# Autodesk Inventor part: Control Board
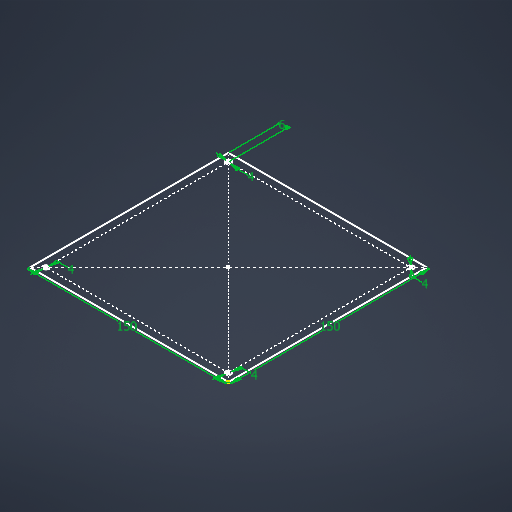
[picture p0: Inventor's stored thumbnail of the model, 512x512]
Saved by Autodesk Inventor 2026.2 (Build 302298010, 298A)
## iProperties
Created: 2026-04
Part Number: Control Board
Material: 일반
Document SubType Name: Modeling
Designer: work
Density: 1 g/cm^3
Appearance: 기본값
Author: work
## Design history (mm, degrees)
sketch "스케치1"
  geometry: L1 (150, -150)-(0, -150); L2 (0, -150)-(0, 0); L3 (0, 0)-(150, 0); L4 (150, 0)-(150, -150); L5 (150, -150)-(0, 0); L6 (0, -150)-(150, 0); L7 (6, -6)-(144, -6); L8 (144, -6)-(144, -144); L9 (144, -144)-(6, -144); L10 (6, -144)-(6, -6); L11 (6, -6)-(144, -144); L12 (144, -6)-(6, -144); C1 r 2 at (144, -6); C2 r 2 at (144, -144); C3 r 2 at (6, -6); C4 r 2 at (6, -144); 2 further points
  constraints: 24 end point, 5 coincident, 4 centre point, 4 midpoint, 4 parallel, 2 horizontal, 2 perpendicular, 1 point on line
  dimensions: "d0" = 150 distance of L2.end L3.end; "d1" = 150 distance of L1.end L2.end; "d2" = 6 distance between parallel lines of L4 L8; "d3" = 4 diameter of C1; "d4" = 4 diameter of C2; "d5" = 4 diameter of C3; "d6" = 4 diameter of C4
